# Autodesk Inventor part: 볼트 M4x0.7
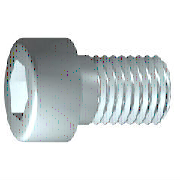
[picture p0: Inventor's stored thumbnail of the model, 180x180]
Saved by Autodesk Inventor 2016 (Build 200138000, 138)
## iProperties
IsCustomPart: 0
Created: 2012-02
Part Number: 볼트 M4x0.7
Material: 스테인리스강
Description: 6각 소켓 머리 캡 나사
Document SubType Name: Modeling
Standard: ISO 4762
Designer: mduedu
Standard Revision: Fourth edition 2004-03-01
Standards Organization: ISO
Language: ko-KR
Size Designation: M4 x 12
Categories: <MemberInstance><Categories><Category DisplayName="조임쇠" InternalName="e4da775c-781d-43d5-af7c-5136215cf5a6" Mnemonic="FSTN"><Category DisplayName="볼트" InternalN
Density: 7.75 g/cm^3
Appearance: 반광택
Author: mduedu
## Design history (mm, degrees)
sketch "스케치1"
  geometry: L1 (-1, 0)-(12, 0); L2 (12, 0)-(12, 2); L3 (12, 2)-(1.75, 2); L4 (1.75, 2)-(1.32, 2); L5 (1.32, 2)-(0, 2); L6 (0, 2)-(0, 3.5); L7 (0, 3.5)-(-4, 3.5); L8 (-4, 3.5)-(-4, 1.732); L9 (-4, 1.732)-(-2, 1.732); L10 (-2, 1.732)-(-1, 0); L11 (-7.2, 0)-(15.2, 0) reference; L12 (0, -0.7)-(0, 4.2) reference; L13 (1.75, 2)-(0, 2)
  constraints: 22 end point, 6 parallel, 2 collinear, 2 perpendicular, 1 horizontal, 1 point on line
  dimensions: "d1" = 10.25 distance from line of L3.end L2 (= GEL); "d2" = 0.42952 distance of L4.end L3.end (computed from GAL); "d3" = 4 distance between parallel lines of L8 L6 (= KOH); "d4" = 2 distance of L8.end L9.end (= INTI); "d5" = 60 deg angle of L10 L1; "d6" = 4 diameter of L3 L1 (= GD); "d7" = 4 diameter of L5 L1 (= BDM); "d8" = 3.4641 diameter of L9 L1 (= 1.1547 x SW); "d9" = 7 diameter of L7 L1 (= KOD); "d26" = 12 distance between parallel lines of L12 L2 (= NLG)
revolve "본체" sketch "스케치1" stored, may be unused: angle "d10" = 90 deg
sketch "스케치2"
  geometry: L1 (0, -4.9)-(0, 4.9) reference; L2 (-4.9, 0)-(4.9, 0) reference; L3 (1.732, 0)-(0.866, -1.5); L4 (0.866, -1.5)-(-0.866, -1.5); L5 (-0.866, -1.5)-(-1.732, 0); L6 (-1.732, 0)-(-0.866, 1.5); L7 (-0.866, 1.5)-(0.866, 1.5); L8 (0.866, 1.5)-(1.732, 0); 2 further points
  constraints: 12 end point, 1 coincident, 1 horizontal alignment, 1 point on line, 12 other
extrude "슬롯" join sketch "스케치2" stored distance "d11" = 10; taper "d12" = 0 deg
workplane "Work Plane1"
fillet "Fillet2" dims "d30" = 0.1 (= R)
body "Solid1"
fillet "모깎기1" dims "d17" = 0.4 (= RR)
feature "스레드" dims "d13" = 10.25 (= GEL), "d14" = 0
chamfer "모따기1" distance "d15" = 0.42941 (= -0.5 x SPD + 0.5 x GD); stored, may be unused: second distance "d16" = 0.42941 (= GUL), angle "d27" = 45 deg
other parameters: "GD" = 4 [user parameter; used in 2 equation terms], "NLG" = 12 [user parameter; used in 1 equation term], "GEL" = 10.25 [user parameter; used in 2 equation terms], "KOD" = 7 [user parameter; used in 1 equation term], "KOH" = 4 [user parameter; used in 1 equation term], "INTI" = 2 [user parameter; used in 1 equation term], "GAL" = 0.42941 (= 0.61345 x PTC) [user parameter; used in 1 equation term], "GUL" = 0.42941 (= 0.61345 x PTC) [user parameter; used in 1 equation term], "BDM" = 4 (= NND) [user parameter; used in 1 equation term], "SW" = 3 [user parameter; used in 2 equation terms], "RR" = 0.4 [user parameter; used in 1 equation term], "SPD" = 3.14117 (= NND - 1.2269 x PTC) [user parameter; used in 1 equation term], "d19" = 0, "d28" = 0, "d29" = 0, "R" = 0.1 [user parameter; used in 1 equation term], "TOA" = 30 deg [user parameter], "GD1" = 3.14117 (= THREADDIA - 1.2269 x PTC) [user parameter], "THREADDIA" = 4 [user parameter; used in 1 equation term], "FAWI" = 45 deg [user parameter], "TPU" = 14.28571 (computed from PTC) [user parameter], "PTC" = 0.7 [user parameter; used in 5 equation terms], "NND" = 4 [user parameter; used in 2 equation terms], "E0" = 3.465 (= 1.155 x SW) [user parameter]
